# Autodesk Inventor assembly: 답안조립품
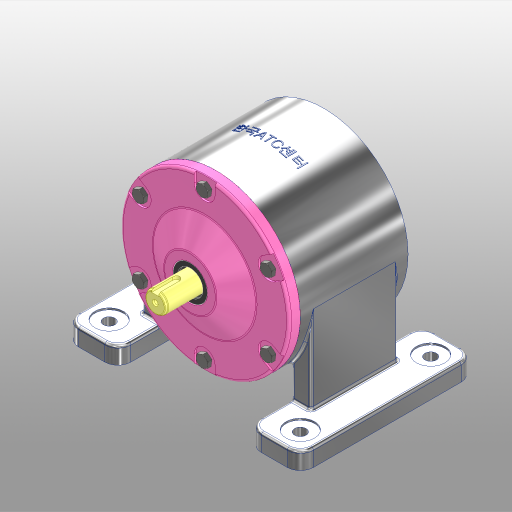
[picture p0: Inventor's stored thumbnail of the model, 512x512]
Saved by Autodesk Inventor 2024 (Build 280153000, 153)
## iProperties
Created: 2025-12
Part Number: 답안조립품
Document SubType Name: Assembly
Designer: Edu09
Author: Edu09
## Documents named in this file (17)
- C:\Users\Edu09\Desktop\751203V1005\답안조립품.iam
- C:\Users\Edu09\Desktop\751203V1005\본체.ipt
- C:\Users\Edu09\Desktop\751203V1005\깊은 홈 볼 베어링 6004.ipt
- C:\Users\Edu09\Desktop\751203V1005\기어 축.ipt
- C:\Users\Edu09\Desktop\751203V1005\C형 멈춤링 구멍용 42.ipt
- C:\Users\Edu09\Desktop\751203V1005\칼라 1.ipt
- C:\Users\Edu09\Desktop\751203V1005\구동 기어.ipt
- C:\Users\Edu09\Desktop\751203V1005\평행 키 6x6x16.ipt
- C:\Users\Edu09\Desktop\751203V1005\엔드 캡.ipt
- C:\Users\Edu09\Desktop\751203V1005\6각 구멍붙이 볼트 M4x10.ipt
- C:\Users\Edu09\Desktop\751203V1005\출력 축.ipt
- C:\Users\Edu09\Desktop\751203V1005\종동 기어.ipt
- C:\Users\Edu09\Desktop\751203V1005\칼라 2.ipt
- C:\Users\Edu09\Desktop\751203V1005\커버.ipt
- C:\Users\Edu09\Desktop\751203V1005\깊은 홈 볼 베어링 6005.ipt
- C:\Users\Edu09\Desktop\751203V1005\오일 실 25 40 8.ipt
- C:\Users\Edu09\Desktop\751203V1005\6각 머리 볼트 M8x20.ipt
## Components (9 placed, 4 different names)
1. C형 멈춤링 구멍용 42:1
2. 구동 기어:1 — 각도:2
3. 6각 구멍붙이 볼트 M4x10:1
4. 6각 머리 볼트 M8x20:1
5. 6각 머리 볼트 M8x20:2
6. 6각 머리 볼트 M8x20:3
7. 6각 머리 볼트 M8x20:4
8. 6각 머리 볼트 M8x20:5
9. 6각 머리 볼트 M8x20:6
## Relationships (1: Angle 1)
- 각도:2 [Angle]: 구동 기어:1
